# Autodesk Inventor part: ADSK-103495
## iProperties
Shininess: 0.0
Created: 2000-10
Part Number: ADSK-103495
Document SubType Name: Modeling
Designer: Administrator
Stock Number: ADSK-103495
Density: 1 g/cm^3
Density: 0.0
Volumn: 0.0
Area: 0.0
PropertySet Name: Model Information
Control State: 0
Master: False
Checked Out: False
Author: Administrator
